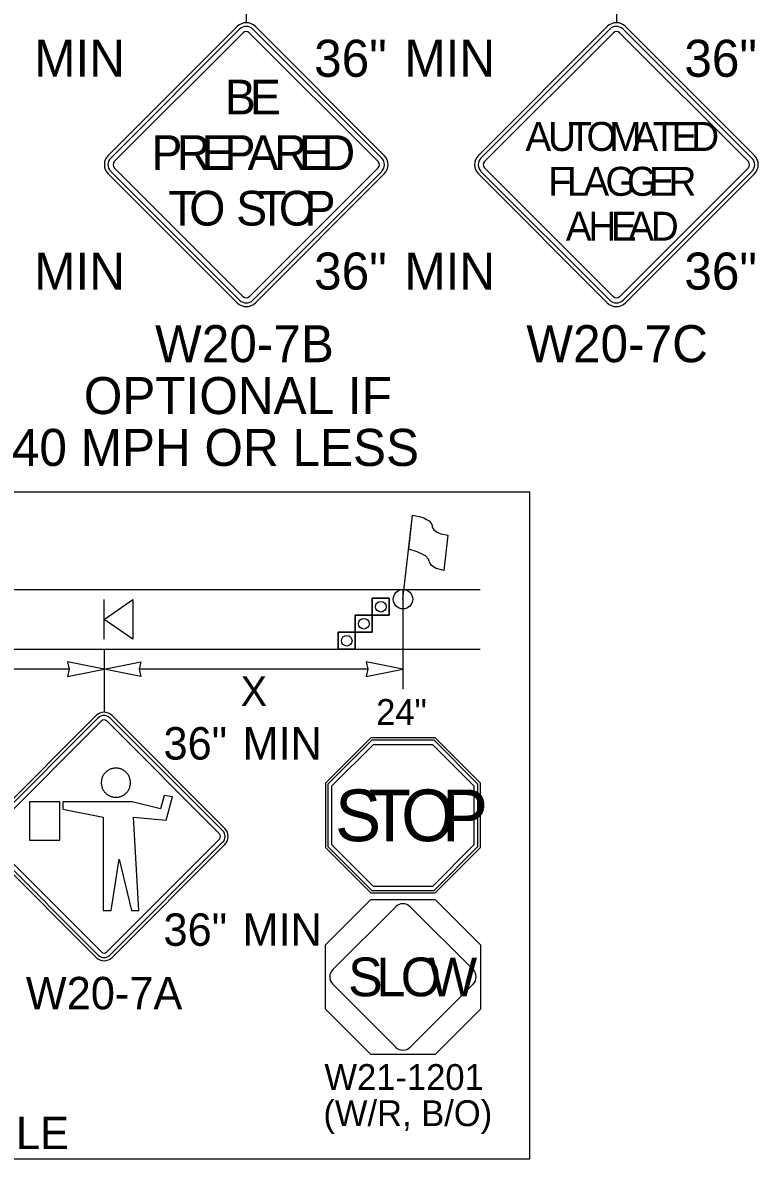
# Model space of a CAD drawing. Extents: x 99999.1 to 100095.7, y 99995 to 100010.7.
# Drawn here: x 100002.194 to 100003.783, y 100003.038 to 100005.492 of the extents above; entities that cross this region are included whole.
import ezdxf

# ---------------------------------------------------------------- set-up
doc = ezdxf.new("R2010")
doc.units = 0
for name, color, linetype in [('RD_ED_ShoulderPavedEdge', 7, 'Continuous'), ('RD_MK_LineEdgeWhite', 7, 'Continuous'), ('TR_SN_ConstructionSigns', 7, 'Continuous'), ('TR_WZ_FlaggingStation', 7, 'Continuous'), ('TR_WZ_PortableSignMountBlk-Org', 7, 'Continuous'), ('TR_WZ_TrafficCone', 7, 'Continuous'), ('TR_WZ_WorkZoneDetails', 7, 'Continuous'), ('TR_WZ_WorkZoneTextCurrent', 7, 'Continuous')]:
    doc.layers.add(name, color=color, linetype=linetype)

msp = doc.modelspace()

# ---------------------------------------------------------------- linework, layer by layer
at = {"layer": 'RD_ED_ShoulderPavedEdge'}
msp.add_line((100000.2089, 100004.1394), (100003.1825, 100004.1394), dxfattribs=at)
at = {"layer": 'RD_MK_LineEdgeWhite'}
msp.add_line((100000.2089, 100004.2685), (100003.1825, 100004.2685), dxfattribs=at)
at = {"layer": 'TR_SN_ConstructionSigns'}
for p, q in [((100002.6568, 100005.4841), (100002.3783, 100005.2057)), ((100002.975, 100005.2057), (100002.6965, 100005.4841)), ((100003.4568, 100005.4841), (100003.1783, 100005.2057)), ((100003.775, 100005.2057), (100003.4965, 100005.4841)), ((100002.6623, 100005.4786), (100002.3839, 100005.2001)), ((100002.3916, 100005.1924), (100002.67, 100005.4708)), ((100002.6833, 100005.4708), (100002.9617, 100005.1924)), ((100002.9694, 100005.2001), (100002.691, 100005.4786)), ((100003.4623, 100005.4786), (100003.1839, 100005.2001)), ((100003.1916, 100005.1924), (100003.47, 100005.4708)), ((100003.4833, 100005.4708), (100003.7617, 100005.1924)), ((100003.7694, 100005.2001), (100003.491, 100005.4786)), ((100002.3783, 100005.1659), (100002.6568, 100004.8875)), ((100002.3839, 100005.1714), (100002.6623, 100004.893)), ((100002.67, 100004.9007), (100002.3916, 100005.1792)), ((100002.9617, 100005.1792), (100002.6833, 100004.9007)), ((100002.691, 100004.893), (100002.9694, 100005.1714)), ((100002.6965, 100004.8875), (100002.975, 100005.1659)), ((100003.1783, 100005.1659), (100003.4568, 100004.8875)), ((100003.1839, 100005.1714), (100003.4623, 100004.893)), ((100003.47, 100004.9007), (100003.1916, 100005.1792)), ((100003.7617, 100005.1792), (100003.4833, 100004.9007)), ((100003.491, 100004.893), (100003.7694, 100005.1714)), ((100003.4965, 100004.8875), (100003.775, 100005.1659)), ((100002.3521, 100003.996), (100002.1084, 100003.7524)), ((100002.3569, 100003.9912), (100002.1133, 100003.7476)), ((100002.6257, 100003.7476), (100002.382, 100003.9912)), ((100002.6305, 100003.7524), (100002.3869, 100003.996)), ((100002.12, 100003.7408), (100002.3637, 100003.9844)), ((100002.3753, 100003.9844), (100002.6189, 100003.7408)), ((100002.946, 100003.948), (100002.8479, 100003.8499)), ((100002.9482, 100003.9428), (100002.8531, 100003.8477)), ((100003.0847, 100003.948), (100002.946, 100003.948)), ((100003.0825, 100003.9428), (100002.9482, 100003.9428)), ((100003.1775, 100003.8477), (100003.0825, 100003.9428)), ((100003.1828, 100003.8499), (100003.0847, 100003.948)), ((100002.8619, 100003.8441), (100002.9518, 100003.934)), ((100002.9518, 100003.934), (100003.0789, 100003.934)), ((100003.0789, 100003.934), (100003.1688, 100003.8441)), ((100002.3663, 100003.8642), (100002.3656, 100003.8626)), ((100002.367, 100003.8657), (100002.3663, 100003.8642)), ((100002.3678, 100003.8672), (100002.367, 100003.8657)), ((100002.3688, 100003.8686), (100002.3678, 100003.8672)), ((100002.3697, 100003.87), (100002.3688, 100003.8686)), ((100002.3707, 100003.8713), (100002.3697, 100003.87)), ((100002.3718, 100003.8725), (100002.3707, 100003.8713)), ((100002.373, 100003.8737), (100002.3718, 100003.8725)), ((100002.3742, 100003.8749), (100002.373, 100003.8737)), ((100002.3755, 100003.8759), (100002.3742, 100003.8749)), ((100002.3769, 100003.8769), (100002.3755, 100003.8759)), ((100002.3783, 100003.8778), (100002.3769, 100003.8769)), ((100002.3797, 100003.8787), (100002.3783, 100003.8778)), ((100002.3812, 100003.8795), (100002.3797, 100003.8787)), ((100002.3827, 100003.8802), (100002.3812, 100003.8795)), ((100002.3843, 100003.8808), (100002.3827, 100003.8802)), ((100002.3859, 100003.8813), (100002.3843, 100003.8808)), ((100002.3875, 100003.8817), (100002.3859, 100003.8813)), ((100002.3892, 100003.8821), (100002.3875, 100003.8817)), ((100002.3908, 100003.8824), (100002.3892, 100003.8821)), ((100002.3925, 100003.8825), (100002.3908, 100003.8824)), ((100002.3942, 100003.8827), (100002.3925, 100003.8825)), ((100002.3959, 100003.8827), (100002.3942, 100003.8827)), ((100002.3975, 100003.8825), (100002.3959, 100003.8827)), ((100002.3992, 100003.8824), (100002.3975, 100003.8825)), ((100002.4008, 100003.8821), (100002.3992, 100003.8824)), ((100002.4025, 100003.8817), (100002.4008, 100003.8821)), ((100002.4041, 100003.8813), (100002.4025, 100003.8817)), ((100002.4057, 100003.8808), (100002.4041, 100003.8813)), ((100002.4072, 100003.8802), (100002.4057, 100003.8808)), ((100002.4088, 100003.8795), (100002.4072, 100003.8802)), ((100002.4103, 100003.8787), (100002.4088, 100003.8795)), ((100002.4117, 100003.8778), (100002.4103, 100003.8787)), ((100002.4131, 100003.8769), (100002.4117, 100003.8778)), ((100002.4145, 100003.8759), (100002.4131, 100003.8769)), ((100002.4157, 100003.8749), (100002.4145, 100003.8759)), ((100002.417, 100003.8737), (100002.4157, 100003.8749)), ((100002.4181, 100003.8725), (100002.417, 100003.8737)), ((100002.4192, 100003.8713), (100002.4181, 100003.8725)), ((100002.4203, 100003.87), (100002.4192, 100003.8713)), ((100002.4213, 100003.8686), (100002.4203, 100003.87)), ((100002.4221, 100003.8672), (100002.4213, 100003.8686)), ((100002.423, 100003.8657), (100002.4221, 100003.8672)), ((100002.4237, 100003.8642), (100002.423, 100003.8657)), ((100002.4243, 100003.8626), (100002.4237, 100003.8642)), ((100002.3637, 100003.8545), (100002.3635, 100003.8528)), ((100002.3635, 100003.8528), (100002.3635, 100003.8511)), ((100002.3635, 100003.8511), (100002.3635, 100003.8495)), ((100002.3635, 100003.8495), (100002.3637, 100003.8478)), ((100002.3639, 100003.8562), (100002.3637, 100003.8545)), ((100002.3637, 100003.8478), (100002.3639, 100003.8461)), ((100002.3642, 100003.8578), (100002.3639, 100003.8562)), ((100002.3639, 100003.8461), (100002.3642, 100003.8445)), ((100002.3646, 100003.8594), (100002.3642, 100003.8578)), ((100002.3642, 100003.8445), (100002.3646, 100003.8429)), ((100002.3651, 100003.861), (100002.3646, 100003.8594)), ((100002.3646, 100003.8429), (100002.3651, 100003.8413)), ((100002.3656, 100003.8626), (100002.3651, 100003.861)), ((100002.3651, 100003.8413), (100002.3656, 100003.8397)), ((100002.3656, 100003.8397), (100002.3663, 100003.8381)), ((100002.4237, 100003.8381), (100002.4243, 100003.8397)), ((100002.4249, 100003.861), (100002.4243, 100003.8626)), ((100002.4243, 100003.8397), (100002.4249, 100003.8413)), ((100002.4254, 100003.8594), (100002.4249, 100003.861)), ((100002.4249, 100003.8413), (100002.4254, 100003.8429)), ((100002.4258, 100003.8578), (100002.4254, 100003.8594)), ((100002.4254, 100003.8429), (100002.4258, 100003.8445)), ((100002.4261, 100003.8562), (100002.4258, 100003.8578)), ((100002.4258, 100003.8445), (100002.4261, 100003.8461)), ((100002.4264, 100003.8545), (100002.4261, 100003.8562)), ((100002.4261, 100003.8461), (100002.4264, 100003.8478)), ((100002.4265, 100003.8528), (100002.4264, 100003.8545)), ((100002.4264, 100003.8478), (100002.4265, 100003.8495)), ((100002.4265, 100003.8511), (100002.4265, 100003.8528)), ((100002.4265, 100003.8495), (100002.4265, 100003.8511)), ((100002.8479, 100003.8499), (100002.8479, 100003.7112)), ((100002.8531, 100003.8477), (100002.8531, 100003.7134)), ((100002.8619, 100003.717), (100002.8619, 100003.8441)), ((100003.1688, 100003.8441), (100003.1688, 100003.717)), ((100003.1775, 100003.7134), (100003.1775, 100003.8477)), ((100003.1828, 100003.7112), (100003.1828, 100003.8499)), ((100002.3663, 100003.8381), (100002.367, 100003.8366)), ((100002.367, 100003.8366), (100002.3678, 100003.8351)), ((100002.3678, 100003.8351), (100002.3688, 100003.8337)), ((100002.3688, 100003.8337), (100002.3697, 100003.8323)), ((100002.3697, 100003.8323), (100002.3707, 100003.831)), ((100002.3707, 100003.831), (100002.3718, 100003.8298)), ((100002.3718, 100003.8298), (100002.373, 100003.8286)), ((100002.373, 100003.8286), (100002.3742, 100003.8274)), ((100002.3742, 100003.8274), (100002.3755, 100003.8264)), ((100002.3755, 100003.8264), (100002.3769, 100003.8253)), ((100002.3769, 100003.8253), (100002.3783, 100003.8244)), ((100002.3783, 100003.8244), (100002.3797, 100003.8236)), ((100002.3797, 100003.8236), (100002.3812, 100003.8228)), ((100002.3812, 100003.8228), (100002.3827, 100003.8221)), ((100002.3827, 100003.8221), (100002.3843, 100003.8215)), ((100002.3843, 100003.8215), (100002.3859, 100003.821)), ((100002.3859, 100003.821), (100002.3875, 100003.8205)), ((100002.3875, 100003.8205), (100002.3892, 100003.8202)), ((100002.3892, 100003.8202), (100002.3908, 100003.8199)), ((100002.3908, 100003.8199), (100002.3925, 100003.8197)), ((100002.3925, 100003.8197), (100002.3942, 100003.8196)), ((100002.3942, 100003.8196), (100002.3959, 100003.8196)), ((100002.3959, 100003.8196), (100002.3975, 100003.8197)), ((100002.3975, 100003.8197), (100002.3992, 100003.8199)), ((100002.3992, 100003.8199), (100002.4008, 100003.8202)), ((100002.4008, 100003.8202), (100002.4025, 100003.8205)), ((100002.4025, 100003.8205), (100002.4041, 100003.821)), ((100002.4041, 100003.821), (100002.4057, 100003.8215)), ((100002.4057, 100003.8215), (100002.4072, 100003.8221)), ((100002.4072, 100003.8221), (100002.4088, 100003.8228)), ((100002.4088, 100003.8228), (100002.4103, 100003.8236)), ((100002.4103, 100003.8236), (100002.4117, 100003.8244)), ((100002.4117, 100003.8244), (100002.4131, 100003.8253)), ((100002.4131, 100003.8253), (100002.4145, 100003.8264)), ((100002.4145, 100003.8264), (100002.4157, 100003.8274)), ((100002.4157, 100003.8274), (100002.417, 100003.8286)), ((100002.417, 100003.8286), (100002.4181, 100003.8298)), ((100002.4181, 100003.8298), (100002.4192, 100003.831)), ((100002.4192, 100003.831), (100002.4203, 100003.8323)), ((100002.4203, 100003.8323), (100002.4213, 100003.8337)), ((100002.4213, 100003.8337), (100002.4221, 100003.8351)), ((100002.4221, 100003.8351), (100002.423, 100003.8366)), ((100002.423, 100003.8366), (100002.4237, 100003.8381)), ((100002.4996, 100003.8235), (100002.4911, 100003.7947)), ((100002.517, 100003.8204), (100002.4996, 100003.8235)), ((100002.5039, 100003.7706), (100002.517, 100003.8204)), ((100002.2083, 100003.8097), (100002.2083, 100003.7268)), ((100002.2742, 100003.8097), (100002.2083, 100003.8097)), ((100002.2742, 100003.7268), (100002.2742, 100003.8097)), ((100002.4302, 100003.8097), (100002.2803, 100003.8097)), ((100002.2803, 100003.8097), (100002.2803, 100003.7939)), ((100002.2803, 100003.7939), (100002.3673, 100003.7766)), ((100002.4911, 100003.7947), (100002.4302, 100003.8097)), ((100002.3673, 100003.7766), (100002.3673, 100003.575)), ((100002.4445, 100003.575), (100002.433, 100003.7767)), ((100002.433, 100003.7767), (100002.5039, 100003.7706)), ((100002.1084, 100003.7176), (100002.3521, 100003.474)), ((100002.1133, 100003.7224), (100002.3569, 100003.4788)), ((100002.3637, 100003.4856), (100002.12, 100003.7292)), ((100002.2083, 100003.7268), (100002.2742, 100003.7268)), ((100002.6189, 100003.7292), (100002.3753, 100003.4856)), ((100002.382, 100003.4788), (100002.6257, 100003.7224)), ((100002.3869, 100003.474), (100002.6305, 100003.7176)), ((100002.9518, 100003.6271), (100002.8619, 100003.717)), ((100003.1688, 100003.717), (100003.0789, 100003.6271)), ((100002.8479, 100003.7112), (100002.946, 100003.6131)), ((100002.8531, 100003.7134), (100002.9482, 100003.6184)), ((100003.0825, 100003.6184), (100003.1775, 100003.7134)), ((100003.0847, 100003.6131), (100003.1828, 100003.7112)), ((100002.385, 100003.575), (100002.4022, 100003.6859)), ((100002.4022, 100003.6859), (100002.4287, 100003.575)), ((100003.0789, 100003.6271), (100002.9518, 100003.6271)), ((100002.946, 100003.6131), (100003.0847, 100003.6131)), ((100002.9482, 100003.6184), (100003.0825, 100003.6184)), ((100002.3673, 100003.575), (100002.385, 100003.575)), ((100002.4287, 100003.575), (100002.4445, 100003.575)), ((100002.9996, 100003.5834), (100002.8637, 100003.4475)), ((100003.167, 100003.4475), (100003.0311, 100003.5834)), ((100002.8637, 100003.416), (100002.9996, 100003.2801)), ((100003.0311, 100003.2801), (100003.167, 100003.416))]:
    msp.add_line(p, q, dxfattribs=at)
msp.add_lwpolyline([(100003.1828, 100003.5011), (100003.1828, 100003.3624), (100003.0847, 100003.2643), (100002.946, 100003.2643), (100002.8479, 100003.3624), (100002.8479, 100003.5011), (100002.946, 100003.5992), (100003.0847, 100003.5992)], close=True, dxfattribs=at)
for centre, radius, start, end in [((100002.6767, 100005.4642), 0.0281, 45, 135), ((100002.6767, 100005.4642), 0.0203, 45, 135), ((100003.4767, 100005.4642), 0.0281, 45, 135), ((100003.4767, 100005.4642), 0.0203, 45, 135), ((100002.6767, 100005.4642), 0.00937, 45, 135), ((100003.4767, 100005.4642), 0.00937, 45, 135), ((100002.3982, 100005.1858), 0.0281, 135, 225), ((100002.3982, 100005.1858), 0.0203, 135, 225), ((100002.3982, 100005.1858), 0.00937, 135, 225), ((100002.9551, 100005.1858), 0.00937, 315, 45), ((100002.9551, 100005.1858), 0.0203, 315, 45), ((100002.9551, 100005.1858), 0.0281, 315, 45), ((100003.1982, 100005.1858), 0.0281, 135, 225), ((100003.1982, 100005.1858), 0.0203, 135, 225), ((100003.1982, 100005.1858), 0.00937, 135, 225), ((100003.7551, 100005.1858), 0.00937, 315, 45), ((100003.7551, 100005.1858), 0.0203, 315, 45), ((100003.7551, 100005.1858), 0.0281, 315, 45), ((100002.6767, 100004.9074), 0.00937, 225, 315), ((100003.4767, 100004.9074), 0.00937, 225, 315), ((100002.6767, 100004.9074), 0.0281, 225, 315), ((100002.6767, 100004.9074), 0.0203, 225, 315), ((100003.4767, 100004.9074), 0.0281, 225, 315), ((100003.4767, 100004.9074), 0.0203, 225, 315), ((100002.3695, 100003.9786), 0.0246, 45, 135), ((100002.3695, 100003.9786), 0.0178, 45, 135), ((100002.3695, 100003.9786), 0.0082, 45, 135), ((100002.6131, 100003.735), 0.0178, 315, 45), ((100002.6131, 100003.735), 0.0246, 315, 45), ((100002.6131, 100003.735), 0.0082, 315, 45), ((100003.0153, 100003.5676), 0.0223, 45, 135), ((100002.3695, 100003.4914), 0.0246, 225, 315), ((100002.3695, 100003.4914), 0.0178, 225, 315), ((100002.3695, 100003.4914), 0.0082, 225, 315), ((100002.8795, 100003.4318), 0.0223, 135, 225), ((100003.1512, 100003.4318), 0.0223, 315, 45), ((100003.0153, 100003.2959), 0.0223, 225, 315)]:
    msp.add_arc(centre, radius, start, end, dxfattribs=at)
at = {"layer": 'TR_WZ_FlaggingStation'}
for p, q in [((100003.0154, 100004.2475), (100003.0361, 100004.429)), ((100003.0277, 100004.3554), (100003.0361, 100004.4292)), ((100003.1123, 100004.3854), (100003.1037, 100004.3097)), ((100003.0277, 100004.3554), (100003.0277, 100004.3554))]:
    msp.add_line(p, q, dxfattribs=at)
for points in [[(100003.0361, 100004.4292), (100003.0398, 100004.4284), (100003.0514, 100004.4262), (100003.0603, 100004.4235), (100003.0665, 100004.4196), (100003.0721, 100004.4165), (100003.0757, 100004.4121), (100003.0785, 100004.407), (100003.0788, 100004.403), (100003.0823, 100004.3971), (100003.0892, 100004.3923), (100003.0973, 100004.3889), (100003.1123, 100004.3854)], [(100003.1037, 100004.3097), (100003.0985, 100004.3106), (100003.087, 100004.3136), (100003.0769, 100004.3204), (100003.0727, 100004.3272), (100003.0702, 100004.3339), (100003.0643, 100004.3409), (100003.0572, 100004.345), (100003.046, 100004.3495), (100003.0277, 100004.3554)]]:
    msp.add_lwpolyline(points, dxfattribs=at)
msp.add_circle((100003.0154, 100004.2475), 0.021, dxfattribs=at)
at = {"layer": 'TR_WZ_PortableSignMountBlk-Org'}
msp.add_line((100002.3695, 100004.1609), (100002.3695, 100004.247), dxfattribs=at)
msp.add_lwpolyline([(100002.3695, 100004.2039), (100002.4313, 100004.247), (100002.4313, 100004.1609)], close=True, dxfattribs=at)
at = {"layer": 'TR_WZ_TrafficCone'}
for points in [[(100002.9491, 100004.2496), (100002.9858, 100004.2496), (100002.9858, 100004.2128), (100002.9491, 100004.2128), (100002.9491, 100004.2496)], [(100002.9491, 100004.2128), (100002.9858, 100004.2128), (100002.9858, 100004.2496), (100002.9491, 100004.2496), (100002.9491, 100004.2128)], [(100002.9123, 100004.2128), (100002.9491, 100004.2128), (100002.9491, 100004.1761), (100002.9123, 100004.1761), (100002.9123, 100004.2128)], [(100002.9123, 100004.1761), (100002.9491, 100004.1761), (100002.9491, 100004.2128), (100002.9123, 100004.2128), (100002.9123, 100004.1761)], [(100002.8756, 100004.1761), (100002.9123, 100004.1761), (100002.9123, 100004.1394), (100002.8756, 100004.1394), (100002.8756, 100004.1761)], [(100002.8756, 100004.1394), (100002.9123, 100004.1394), (100002.9123, 100004.1761), (100002.8756, 100004.1761), (100002.8756, 100004.1394)]]:
    msp.add_lwpolyline(points, dxfattribs=at)
for centre in [(100002.9674, 100004.2312), (100002.9307, 100004.1945), (100002.8939, 100004.1577)]:
    msp.add_circle(centre, 0.0115, dxfattribs=at)
at = {"layer": 'TR_WZ_WorkZoneDetails'}
for p, q in [((100002.6767, 100005.7323), (100002.6767, 100005.4923)), ((100003.4767, 100005.7323), (100003.4767, 100005.4923)), ((100003.0154, 100004.2685), (100003.0154, 100004.0532)), ((100002.3695, 100004.1394), (100002.3695, 100004.0032)), ((100002.2938, 100004.0963), (100001.7992, 100004.0963)), ((100002.9397, 100004.0963), (100002.4452, 100004.0963))]:
    msp.add_line(p, q, dxfattribs=at)
for points in [[(100002.3695, 100004.0963), (100002.2901, 100004.1119), (100002.2938, 100004.0963), (100002.2901, 100004.0807)], [(100002.3695, 100004.0963), (100002.4488, 100004.1119), (100002.4452, 100004.0963), (100002.4488, 100004.0807)], [(100003.0154, 100004.0963), (100002.9361, 100004.1119), (100002.9397, 100004.0963), (100002.9361, 100004.0807)]]:
    msp.add_lwpolyline(points, close=True, dxfattribs=at)
at = {"layer": 'TR_WZ_WorkZoneTextCurrent'}
msp.add_lwpolyline([(100000.1, 100004.4792), (100003.2886, 100004.4792), (100003.2886, 100003.0379), (100000.1, 100003.0379)], close=True, dxfattribs=at)

# ---------------------------------------------------------------- texts
at = {"layer": 'TR_SN_ConstructionSigns'}
for s, height, p in [('MIN', 0.08, (100002.2184, 100005.3756)), ('36"', 0.08, (100002.8234, 100005.3756)), ('MIN', 0.08, (100003.0184, 100005.3756)), ('36"', 0.08, (100003.6234, 100005.3756)), ('MIN', 0.08, (100002.2184, 100004.916)), ('36"', 0.08, (100002.8234, 100004.916)), ('MIN', 0.08, (100003.0184, 100004.916)), ('36"', 0.08, (100003.6234, 100004.916)), ('W20-7B', 0.08, (100002.4796, 100004.7592)), ('W20-7C', 0.08, (100003.2819, 100004.7592)), ('OPTIONAL IF', 0.08, (100002.3257, 100004.6472)), ('40 MPH OR LESS', 0.08, (100002.1702, 100004.5352)), ('36"', 0.07, (100002.4979, 100003.9011)), ('MIN', 0.07, (100002.6685, 100003.9011)), ('36"', 0.07, (100002.4979, 100003.4989)), ('MIN', 0.07, (100002.6685, 100003.4989)), ('W20-7A', 0.07, (100002.2004, 100003.3618)), ('W21-1201', 0.05581, (100002.8457, 100003.1876)), ('(W/R, B/O)', 0.05581, (100002.8434, 100003.1095))]:
    msp.add_text(s, height=height, rotation=360, dxfattribs=at).set_placement(p)
for s, height, p in [('B', 0.075, (100002.6304, 100005.2943)), ('E', 0.075, (100002.6847, 100005.2943)), ('A', 0.0625, (100003.2801, 100005.2155)), ('U', 0.0625, (100003.3288, 100005.2155)), ('T', 0.0625, (100003.3726, 100005.2155)), ('O', 0.0625, (100003.412, 100005.2155)), ('M', 0.0625, (100003.4613, 100005.2155)), ('A', 0.0625, (100003.5113, 100005.2155)), ('T', 0.0625, (100003.5551, 100005.2155)), ('E', 0.0625, (100003.5957, 100005.2155)), ('D', 0.0625, (100003.6382, 100005.2155)), ('P', 0.075, (100002.4718, 100005.1743)), ('R', 0.075, (100002.527, 100005.1743)), ('E', 0.075, (100002.5802, 100005.1743)), ('P', 0.075, (100002.6297, 100005.1743)), ('A', 0.075, (100002.6796, 100005.1743)), ('R', 0.075, (100002.7368, 100005.1743)), ('E', 0.075, (100002.7901, 100005.1743)), ('D', 0.075, (100002.8396, 100005.1743)), ('F', 0.0625, (100003.3292, 100005.1186)), ('L', 0.0625, (100003.3698, 100005.1186)), ('A', 0.0625, (100003.4054, 100005.1186)), ('G', 0.0625, (100003.4529, 100005.1186)), ('G', 0.0625, (100003.4992, 100005.1186)), ('E', 0.0625, (100003.5467, 100005.1186)), ('R', 0.0625, (100003.5892, 100005.1186)), ('T', 0.075, (100002.5084, 100005.0543)), ('O', 0.075, (100002.5535, 100005.0543)), ('S', 0.075, (100002.655, 100005.0543)), ('T', 0.075, (100002.7021, 100005.0543)), ('O', 0.075, (100002.7472, 100005.0543)), ('P', 0.075, (100002.8029, 100005.0543)), ('A', 0.0625, (100003.3673, 100005.0217)), ('H', 0.0625, (100003.416, 100005.0217)), ('E', 0.0625, (100003.4648, 100005.0217)), ('A', 0.0625, (100003.5023, 100005.0217)), ('D', 0.0625, (100003.551, 100005.0217)), ('24"', 0.05581, (100002.9574, 100003.9759)), ('S', 0.1116, (100002.8686, 100003.7248)), ('T', 0.1116, (100002.9411, 100003.7248)), ('O', 0.1116, (100003.0114, 100003.7248)), ('P', 0.1116, (100003.0996, 100003.7248)), ('S', 0.0837, (100002.8969, 100003.3899)), ('L', 0.0837, (100002.958, 100003.3899)), ('O', 0.0837, (100003.0107, 100003.3899)), ('W', 0.0837, (100003.0702, 100003.3899))]:
    msp.add_text(s, height=height, dxfattribs=at).set_placement(p)
at = {"layer": 'TR_WZ_WorkZoneTextCurrent'}
for s, height, p in [('X', 0.0646, (100002.6644, 100004.0166)), ('UPDATE SIGNAGE & USE STOP/SLOW PADDLE', 0.07, (100000.1713, 100003.0599))]:
    msp.add_text(s, height=height, dxfattribs=at).set_placement(p)

doc.saveas('drawing.dxf')
